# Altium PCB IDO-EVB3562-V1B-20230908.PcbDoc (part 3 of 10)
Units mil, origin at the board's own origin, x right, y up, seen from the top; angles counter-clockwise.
Board outline 5314.96 x 3543.31 mil, 4 copper layers (TOP, L2-VCC, L3-GND, BOTTOM), stack 28.8 mil thick; 747 components, 560 nets, 2514 pads, 1964 vias.
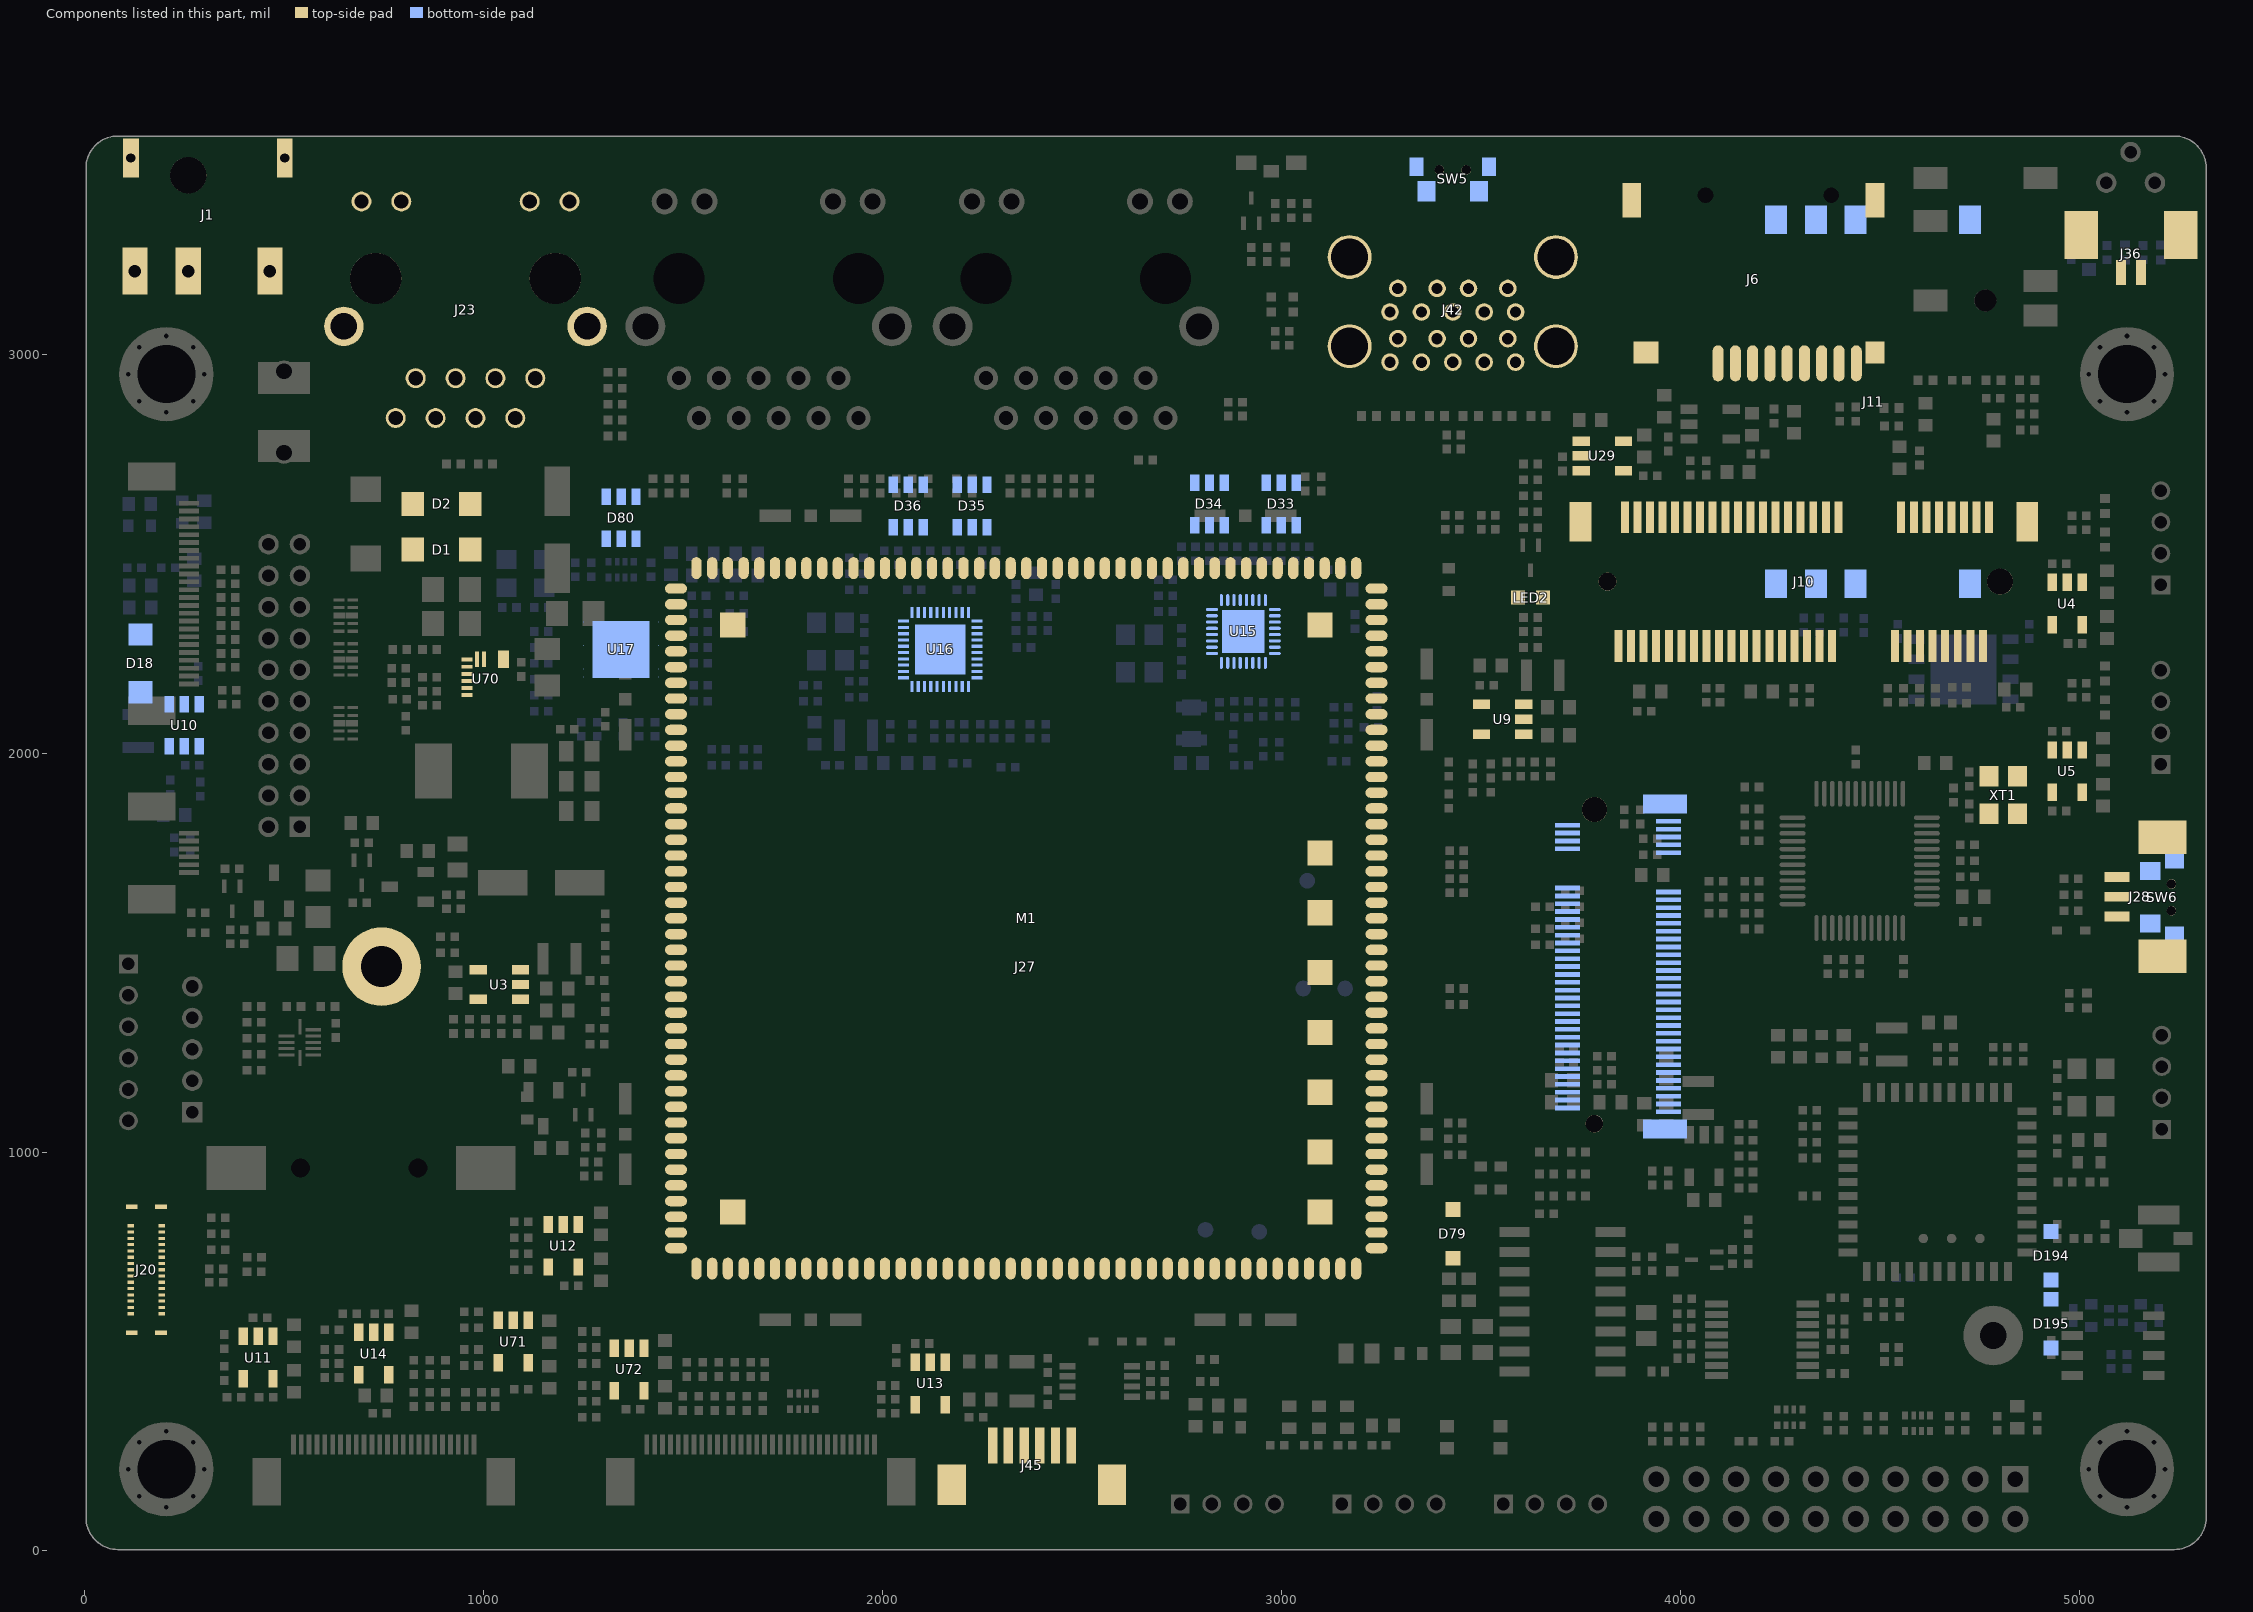
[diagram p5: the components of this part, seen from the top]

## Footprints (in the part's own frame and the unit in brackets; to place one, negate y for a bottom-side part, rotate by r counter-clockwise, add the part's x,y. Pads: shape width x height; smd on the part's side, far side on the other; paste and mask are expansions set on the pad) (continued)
SILKSCREEN_BOTTOM#9 [mm] "SILKSCREEN_BOTTOM"
  oct 0.025x0.025 smd: 1(-2.4,1.751) 2(-2.4,1.251) 3(-2.4,0.751) 4(-2.4,0.25) 5(-2.4,-0.25) 6(-2.4,-0.751) 7(-2.4,-1.251) 8(-2.4,-1.751) 9(-1.751,-2.4) 10(-1.251,-2.4) 11(-0.751,-2.4) 12(-0.25,-2.4) 13(0.25,-2.4) 14(0.751,-2.4) 15(1.251,-2.4) 16(1.751,-2.4) 17(2.4,-1.751) 18(2.4,-1.251) 19(2.4,-0.751) 20(2.4,-0.25) 21(2.4,0.25) 22(2.4,0.751) 23(2.4,1.251) 24(2.4,1.751) 25(1.751,2.4) 26(1.251,2.4) 27(0.751,2.4) 28(0.25,2.4) 29(-0.25,2.4) 30(-0.751,2.4) 31(-1.251,2.4) 32(-1.751,2.4)
  rect 3.607x3.607 smd: 33(0,0)
  TOP region: -1.612,-2.197 -1.612,-2.756 -1.891,-2.756 -1.891,-2.197 -1.891,-2.184 -1.891,-2.184 -1.89,-2.172 -1.889,-2.16 -1.886,-2.148 -1.883,-2.137 -1.878,-2.125 -1.872,-2.115 -1.866,-2.104 -1.858,-2.095 -1.85,-2.086 -1.841,-2.077 -1.831,-2.07 -1.821,-2.063 -1.81,-2.058 -1.799,-2.053 -1.787,-2.049 -1.776,-2.047 -1.763,-2.045 -1.751,-2.045 -1.739,-2.045 -1.727,-2.047 -1.715,-2.049 -1.704,-2.053 -1.692,-2.058 -1.681,-2.063 -1.671,-2.07 -1.662,-2.077 -1.653,-2.086 -1.644,-2.095 -1.637,-2.104 -1.63,-2.115 -1.625,-2.125 -1.62,-2.137 -1.616,-2.148 -1.614,-2.16 -1.612,-2.172 -1.612,-2.184 -1.612,-2.197
  TOP region: -1.612,-2.197 -1.612,-2.756 -1.891,-2.756 -1.891,-2.197 -1.891,-2.184 -1.891,-2.184 -1.89,-2.172 -1.889,-2.16 -1.886,-2.148 -1.883,-2.137 -1.878,-2.125 -1.872,-2.115 -1.866,-2.104 -1.858,-2.095 -1.85,-2.086 -1.841,-2.077 -1.831,-2.07 -1.821,-2.063 -1.81,-2.058 -1.799,-2.053 -1.787,-2.049 -1.776,-2.047 -1.763,-2.045 -1.751,-2.045 -1.739,-2.045 -1.727,-2.047 -1.715,-2.049 -1.704,-2.053 -1.692,-2.058 -1.681,-2.063 -1.671,-2.07 -1.662,-2.077 -1.653,-2.086 -1.644,-2.095 -1.637,-2.104 -1.63,-2.115 -1.625,-2.125 -1.62,-2.137 -1.616,-2.148 -1.614,-2.16 -1.612,-2.172 -1.612,-2.184 -1.612,-2.197
  TOP region: -1.111,-2.197 -1.111,-2.756 -1.391,-2.756 -1.391,-2.197 -1.391,-2.184 -1.391,-2.184 -1.39,-2.172 -1.389,-2.16 -1.386,-2.148 -1.382,-2.137 -1.378,-2.125 -1.372,-2.115 -1.365,-2.104 -1.358,-2.095 -1.35,-2.086 -1.341,-2.077 -1.331,-2.07 -1.321,-2.063 -1.31,-2.058 -1.299,-2.053 -1.287,-2.049 -1.275,-2.047 -1.263,-2.045 -1.251,-2.045 -1.239,-2.045 -1.227,-2.047 -1.215,-2.049 -1.203,-2.053 -1.192,-2.058 -1.181,-2.063 -1.171,-2.07 -1.161,-2.077 -1.152,-2.086 -1.144,-2.095 -1.137,-2.104 -1.13,-2.115 -1.124,-2.125 -1.12,-2.137 -1.116,-2.148 -1.113,-2.16 -1.112,-2.172 -1.111,-2.184 -1.111,-2.197
  TOP region: -1.111,-2.197 -1.111,-2.756 -1.391,-2.756 -1.391,-2.197 -1.391,-2.184 -1.391,-2.184 -1.39,-2.172 -1.389,-2.16 -1.386,-2.148 -1.382,-2.137 -1.378,-2.125 -1.372,-2.115 -1.365,-2.104 -1.358,-2.095 -1.35,-2.086 -1.341,-2.077 -1.331,-2.07 -1.321,-2.063 -1.31,-2.058 -1.299,-2.053 -1.287,-2.049 -1.275,-2.047 -1.263,-2.045 -1.251,-2.045 -1.239,-2.045 -1.227,-2.047 -1.215,-2.049 -1.203,-2.053 -1.192,-2.058 -1.181,-2.063 -1.171,-2.07 -1.161,-2.077 -1.152,-2.086 -1.144,-2.095 -1.137,-2.104 -1.13,-2.115 -1.124,-2.125 -1.12,-2.137 -1.116,-2.148 -1.113,-2.16 -1.112,-2.172 -1.111,-2.184 -1.111,-2.197
  TOP region: -0.611,-2.197 -0.611,-2.756 -0.89,-2.756 -0.89,-2.197 -0.89,-2.184 -0.89,-2.184 -0.89,-2.172 -0.888,-2.16 -0.886,-2.148 -0.882,-2.137 -0.877,-2.125 -0.872,-2.115 -0.865,-2.104 -0.858,-2.095 -0.849,-2.086 -0.84,-2.077 -0.831,-2.07 -0.82,-2.063 -0.81,-2.058 -0.798,-2.053 -0.787,-2.049 -0.775,-2.047 -0.763,-2.045 -0.751,-2.045 -0.738,-2.045 -0.726,-2.047 -0.714,-2.049 -0.703,-2.053 -0.692,-2.058 -0.681,-2.063 -0.67,-2.07 -0.661,-2.077 -0.652,-2.086 -0.644,-2.095 -0.636,-2.104 -0.63,-2.115 -0.624,-2.125 -0.619,-2.137 -0.616,-2.148 -0.613,-2.16 -0.611,-2.172 -0.611,-2.184 -0.611,-2.197
  TOP region: -0.611,-2.197 -0.611,-2.756 -0.89,-2.756 -0.89,-2.197 -0.89,-2.184 -0.89,-2.184 -0.89,-2.172 -0.888,-2.16 -0.886,-2.148 -0.882,-2.137 -0.877,-2.125 -0.872,-2.115 -0.865,-2.104 -0.858,-2.095 -0.849,-2.086 -0.84,-2.077 -0.831,-2.07 -0.82,-2.063 -0.81,-2.058 -0.798,-2.053 -0.787,-2.049 -0.775,-2.047 -0.763,-2.045 -0.751,-2.045 -0.738,-2.045 -0.726,-2.047 -0.714,-2.049 -0.703,-2.053 -0.692,-2.058 -0.681,-2.063 -0.67,-2.07 -0.661,-2.077 -0.652,-2.086 -0.644,-2.095 -0.636,-2.104 -0.63,-2.115 -0.624,-2.125 -0.619,-2.137 -0.616,-2.148 -0.613,-2.16 -0.611,-2.172 -0.611,-2.184 -0.611,-2.197
  TOP region: -0.11,-2.197 -0.11,-2.756 -0.39,-2.756 -0.39,-2.197 -0.39,-2.184 -0.39,-2.184 -0.389,-2.172 -0.388,-2.16 -0.385,-2.148 -0.381,-2.137 -0.377,-2.125 -0.371,-2.115 -0.365,-2.104 -0.357,-2.095 -0.349,-2.086 -0.34,-2.077 -0.33,-2.07 -0.32,-2.063 -0.309,-2.058 -0.298,-2.053 -0.286,-2.049 -0.274,-2.047 -0.262,-2.045 -0.25,-2.045 -0.238,-2.045 -0.226,-2.047 -0.214,-2.049 -0.202,-2.053 -0.191,-2.058 -0.18,-2.063 -0.17,-2.07 -0.16,-2.077 -0.151,-2.086 -0.143,-2.095 -0.136,-2.104 -0.129,-2.115 -0.124,-2.125 -0.119,-2.137 -0.115,-2.148 -0.113,-2.16 -0.111,-2.172 -0.11,-2.184 -0.11,-2.197
  TOP region: -0.11,-2.197 -0.11,-2.756 -0.39,-2.756 -0.39,-2.197 -0.39,-2.184 -0.39,-2.184 -0.389,-2.172 -0.388,-2.16 -0.385,-2.148 -0.381,-2.137 -0.377,-2.125 -0.371,-2.115 -0.365,-2.104 -0.357,-2.095 -0.349,-2.086 -0.34,-2.077 -0.33,-2.07 -0.32,-2.063 -0.309,-2.058 -0.298,-2.053 -0.286,-2.049 -0.274,-2.047 -0.262,-2.045 -0.25,-2.045 -0.238,-2.045 -0.226,-2.047 -0.214,-2.049 -0.202,-2.053 -0.191,-2.058 -0.18,-2.063 -0.17,-2.07 -0.16,-2.077 -0.151,-2.086 -0.143,-2.095 -0.136,-2.104 -0.129,-2.115 -0.124,-2.125 -0.119,-2.137 -0.115,-2.148 -0.113,-2.16 -0.111,-2.172 -0.11,-2.184 -0.11,-2.197
  TOP region: 0.39,-2.197 0.39,-2.756 0.11,-2.756 0.11,-2.197 0.11,-2.184 0.11,-2.184 0.111,-2.172 0.113,-2.16 0.115,-2.148 0.119,-2.137 0.124,-2.125 0.129,-2.115 0.136,-2.104 0.143,-2.095 0.151,-2.086 0.16,-2.077 0.17,-2.07 0.18,-2.063 0.191,-2.058 0.202,-2.053 0.214,-2.049 0.226,-2.047 0.238,-2.045 0.25,-2.045 0.262,-2.045 0.274,-2.047 0.286,-2.049 0.298,-2.053 0.309,-2.058 0.32,-2.063 0.33,-2.07 0.34,-2.077 0.349,-2.086 0.357,-2.095 0.365,-2.104 0.371,-2.115 0.377,-2.125 0.381,-2.137 0.385,-2.148 0.388,-2.16 0.389,-2.172 0.39,-2.184 0.39,-2.197
  TOP region: 0.39,-2.197 0.39,-2.756 0.11,-2.756 0.11,-2.197 0.11,-2.184 0.11,-2.184 0.111,-2.172 0.113,-2.16 0.115,-2.148 0.119,-2.137 0.124,-2.125 0.129,-2.115 0.136,-2.104 0.143,-2.095 0.151,-2.086 0.16,-2.077 0.17,-2.07 0.18,-2.063 0.191,-2.058 0.202,-2.053 0.214,-2.049 0.226,-2.047 0.238,-2.045 0.25,-2.045 0.262,-2.045 0.274,-2.047 0.286,-2.049 0.298,-2.053 0.309,-2.058 0.32,-2.063 0.33,-2.07 0.34,-2.077 0.349,-2.086 0.357,-2.095 0.365,-2.104 0.371,-2.115 0.377,-2.125 0.381,-2.137 0.385,-2.148 0.388,-2.16 0.389,-2.172 0.39,-2.184 0.39,-2.197
  TOP region: 0.89,-2.197 0.89,-2.756 0.611,-2.756 0.611,-2.197 0.611,-2.184 0.611,-2.184 0.611,-2.172 0.613,-2.16 0.616,-2.148 0.619,-2.137 0.624,-2.125 0.63,-2.115 0.636,-2.104 0.644,-2.095 0.652,-2.086 0.661,-2.077 0.67,-2.07 0.681,-2.063 0.692,-2.058 0.703,-2.053 0.714,-2.049 0.726,-2.047 0.738,-2.045 0.751,-2.045 0.763,-2.045 0.775,-2.047 0.787,-2.049 0.798,-2.053 0.81,-2.058 0.82,-2.063 0.831,-2.07 0.84,-2.077 0.849,-2.086 0.858,-2.095 0.865,-2.104 0.872,-2.115 0.877,-2.125 0.882,-2.137 0.886,-2.148 0.888,-2.16 0.89,-2.172 0.89,-2.184 0.89,-2.197
  TOP region: 0.89,-2.197 0.89,-2.756 0.611,-2.756 0.611,-2.197 0.611,-2.184 0.611,-2.184 0.611,-2.172 0.613,-2.16 0.616,-2.148 0.619,-2.137 0.624,-2.125 0.63,-2.115 0.636,-2.104 0.644,-2.095 0.652,-2.086 0.661,-2.077 0.67,-2.07 0.681,-2.063 0.692,-2.058 0.703,-2.053 0.714,-2.049 0.726,-2.047 0.738,-2.045 0.751,-2.045 0.763,-2.045 0.775,-2.047 0.787,-2.049 0.798,-2.053 0.81,-2.058 0.82,-2.063 0.831,-2.07 0.84,-2.077 0.849,-2.086 0.858,-2.095 0.865,-2.104 0.872,-2.115 0.877,-2.125 0.882,-2.137 0.886,-2.148 0.888,-2.16 0.89,-2.172 0.89,-2.184 0.89,-2.197
  TOP region: 1.391,-2.197 1.391,-2.756 1.111,-2.756 1.111,-2.197 1.111,-2.184 1.111,-2.184 1.112,-2.172 1.113,-2.16 1.116,-2.148 1.12,-2.137 1.124,-2.125 1.13,-2.115 1.137,-2.104 1.144,-2.095 1.152,-2.086 1.161,-2.077 1.171,-2.07 1.181,-2.063 1.192,-2.058 1.203,-2.053 1.215,-2.049 1.227,-2.047 1.239,-2.045 1.251,-2.045 1.263,-2.045 1.275,-2.047 1.287,-2.049 1.299,-2.053 1.31,-2.058 1.321,-2.063 1.331,-2.07 1.341,-2.077 1.35,-2.086 1.358,-2.095 1.365,-2.104 1.372,-2.115 1.378,-2.125 1.382,-2.137 1.386,-2.148 1.389,-2.16 1.39,-2.172 1.391,-2.184 1.391,-2.197
  TOP region: 1.391,-2.197 1.391,-2.756 1.111,-2.756 1.111,-2.197 1.111,-2.184 1.111,-2.184 1.112,-2.172 1.113,-2.16 1.116,-2.148 1.12,-2.137 1.124,-2.125 1.13,-2.115 1.137,-2.104 1.144,-2.095 1.152,-2.086 1.161,-2.077 1.171,-2.07 1.181,-2.063 1.192,-2.058 1.203,-2.053 1.215,-2.049 1.227,-2.047 1.239,-2.045 1.251,-2.045 1.263,-2.045 1.275,-2.047 1.287,-2.049 1.299,-2.053 1.31,-2.058 1.321,-2.063 1.331,-2.07 1.341,-2.077 1.35,-2.086 1.358,-2.095 1.365,-2.104 1.372,-2.115 1.378,-2.125 1.382,-2.137 1.386,-2.148 1.389,-2.16 1.39,-2.172 1.391,-2.184 1.391,-2.197
  TOP region: 1.891,-2.197 1.891,-2.756 1.612,-2.756 1.612,-2.197 1.612,-2.184 1.612,-2.184 1.612,-2.172 1.614,-2.16 1.616,-2.148 1.62,-2.137 1.625,-2.125 1.63,-2.115 1.637,-2.104 1.644,-2.095 1.653,-2.086 1.662,-2.077 1.671,-2.07 1.681,-2.063 1.692,-2.058 1.704,-2.053 1.715,-2.049 1.727,-2.047 1.739,-2.045 1.751,-2.045 1.763,-2.045 1.776,-2.047 1.787,-2.049 1.799,-2.053 1.81,-2.058 1.821,-2.063 1.831,-2.07 1.841,-2.077 1.85,-2.086 1.858,-2.095 1.866,-2.104 1.872,-2.115 1.878,-2.125 1.883,-2.137 1.886,-2.148 1.889,-2.16 1.89,-2.172 1.891,-2.184 1.891,-2.197
  TOP region: 1.891,-2.197 1.891,-2.756 1.612,-2.756 1.612,-2.197 1.612,-2.184 1.612,-2.184 1.612,-2.172 1.614,-2.16 1.616,-2.148 1.62,-2.137 1.625,-2.125 1.63,-2.115 1.637,-2.104 1.644,-2.095 1.653,-2.086 1.662,-2.077 1.671,-2.07 1.681,-2.063 1.692,-2.058 1.704,-2.053 1.715,-2.049 1.727,-2.047 1.739,-2.045 1.751,-2.045 1.763,-2.045 1.776,-2.047 1.787,-2.049 1.799,-2.053 1.81,-2.058 1.821,-2.063 1.831,-2.07 1.841,-2.077 1.85,-2.086 1.858,-2.095 1.866,-2.104 1.872,-2.115 1.878,-2.125 1.883,-2.137 1.886,-2.148 1.889,-2.16 1.89,-2.172 1.891,-2.184 1.891,-2.197
  TOP region: -2.197,-1.891 -2.756,-1.891 -2.756,-1.612 -2.197,-1.612 -2.184,-1.612 -2.184,-1.612 -2.172,-1.612 -2.16,-1.614 -2.148,-1.616 -2.137,-1.62 -2.125,-1.625 -2.115,-1.63 -2.104,-1.637 -2.095,-1.644 -2.086,-1.653 -2.077,-1.662 -2.07,-1.671 -2.063,-1.681 -2.058,-1.692 -2.053,-1.704 -2.049,-1.715 -2.047,-1.727 -2.045,-1.739 -2.045,-1.751 -2.045,-1.763 -2.047,-1.776 -2.049,-1.787 -2.053,-1.799 -2.058,-1.81 -2.063,-1.821 -2.07,-1.831 -2.077,-1.841 -2.086,-1.85 -2.095,-1.858 -2.104,-1.866 -2.115,-1.872 -2.125,-1.878 -2.137,-1.883 -2.148,-1.886 -2.16,-1.889 -2.172,-1.89 -2.184,-1.891 -2.197,-1.891
  TOP region: -2.197,-1.891 -2.756,-1.891 -2.756,-1.612 -2.197,-1.612 -2.184,-1.612 -2.184,-1.612 -2.172,-1.612 -2.16,-1.614 -2.148,-1.616 -2.137,-1.62 -2.125,-1.625 -2.115,-1.63 -2.104,-1.637 -2.095,-1.644 -2.086,-1.653 -2.077,-1.662 -2.07,-1.671 -2.063,-1.681 -2.058,-1.692 -2.053,-1.704 -2.049,-1.715 -2.047,-1.727 -2.045,-1.739 -2.045,-1.751 -2.045,-1.763 -2.047,-1.776 -2.049,-1.787 -2.053,-1.799 -2.058,-1.81 -2.063,-1.821 -2.07,-1.831 -2.077,-1.841 -2.086,-1.85 -2.095,-1.858 -2.104,-1.866 -2.115,-1.872 -2.125,-1.878 -2.137,-1.883 -2.148,-1.886 -2.16,-1.889 -2.172,-1.89 -2.184,-1.891 -2.197,-1.891
  TOP region: 2.197,-1.612 2.756,-1.612 2.756,-1.891 2.197,-1.891 2.184,-1.891 2.184,-1.891 2.172,-1.89 2.16,-1.889 2.148,-1.886 2.137,-1.883 2.125,-1.878 2.115,-1.872 2.104,-1.866 2.095,-1.858 2.086,-1.85 2.077,-1.841 2.07,-1.831 2.063,-1.821 2.058,-1.81 2.053,-1.799 2.049,-1.787 2.047,-1.776 2.045,-1.763 2.045,-1.751 2.045,-1.739 2.047,-1.727 2.049,-1.715 2.053,-1.704 2.058,-1.692 2.063,-1.681 2.07,-1.671 2.077,-1.662 2.086,-1.653 2.095,-1.644 2.104,-1.637 2.115,-1.63 2.125,-1.625 2.137,-1.62 2.148,-1.616 2.16,-1.614 2.172,-1.612 2.184,-1.612 2.197,-1.612
  TOP region: 2.197,-1.612 2.756,-1.612 2.756,-1.891 2.197,-1.891 2.184,-1.891 2.184,-1.891 2.172,-1.89 2.16,-1.889 2.148,-1.886 2.137,-1.883 2.125,-1.878 2.115,-1.872 2.104,-1.866 2.095,-1.858 2.086,-1.85 2.077,-1.841 2.07,-1.831 2.063,-1.821 2.058,-1.81 2.053,-1.799 2.049,-1.787 2.047,-1.776 2.045,-1.763 2.045,-1.751 2.045,-1.739 2.047,-1.727 2.049,-1.715 2.053,-1.704 2.058,-1.692 2.063,-1.681 2.07,-1.671 2.077,-1.662 2.086,-1.653 2.095,-1.644 2.104,-1.637 2.115,-1.63 2.125,-1.625 2.137,-1.62 2.148,-1.616 2.16,-1.614 2.172,-1.612 2.184,-1.612 2.197,-1.612
  TOP region: -2.197,-1.391 -2.756,-1.391 -2.756,-1.111 -2.197,-1.111 -2.184,-1.111 -2.184,-1.111 -2.172,-1.112 -2.16,-1.113 -2.148,-1.116 -2.137,-1.12 -2.125,-1.124 -2.115,-1.13 -2.104,-1.137 -2.095,-1.144 -2.086,-1.152 -2.077,-1.161 -2.07,-1.171 -2.063,-1.181 -2.058,-1.192 -2.053,-1.203 -2.049,-1.215 -2.047,-1.227 -2.045,-1.239 -2.045,-1.251 -2.045,-1.263 -2.047,-1.275 -2.049,-1.287 -2.053,-1.299 -2.058,-1.31 -2.063,-1.321 -2.07,-1.331 -2.077,-1.341 -2.086,-1.35 -2.095,-1.358 -2.104,-1.365 -2.115,-1.372 -2.125,-1.378 -2.137,-1.382 -2.148,-1.386 -2.16,-1.389 -2.172,-1.39 -2.184,-1.391 -2.197,-1.391
  TOP region: -2.197,-1.391 -2.756,-1.391 -2.756,-1.111 -2.197,-1.111 -2.184,-1.111 -2.184,-1.111 -2.172,-1.112 -2.16,-1.113 -2.148,-1.116 -2.137,-1.12 -2.125,-1.124 -2.115,-1.13 -2.104,-1.137 -2.095,-1.144 -2.086,-1.152 -2.077,-1.161 -2.07,-1.171 -2.063,-1.181 -2.058,-1.192 -2.053,-1.203 -2.049,-1.215 -2.047,-1.227 -2.045,-1.239 -2.045,-1.251 -2.045,-1.263 -2.047,-1.275 -2.049,-1.287 -2.053,-1.299 -2.058,-1.31 -2.063,-1.321 -2.07,-1.331 -2.077,-1.341 -2.086,-1.35 -2.095,-1.358 -2.104,-1.365 -2.115,-1.372 -2.125,-1.378 -2.137,-1.382 -2.148,-1.386 -2.16,-1.389 -2.172,-1.39 -2.184,-1.391 -2.197,-1.391
  TOP region: 2.197,-1.111 2.756,-1.111 2.756,-1.391 2.197,-1.391 2.184,-1.391 2.184,-1.391 2.172,-1.39 2.16,-1.389 2.148,-1.386 2.137,-1.382 2.125,-1.378 2.115,-1.372 2.104,-1.365 2.095,-1.358 2.086,-1.35 2.077,-1.341 2.07,-1.331 2.063,-1.321 2.058,-1.31 2.053,-1.299 2.049,-1.287 2.047,-1.275 2.045,-1.263 2.045,-1.251 2.045,-1.239 2.047,-1.227 2.049,-1.215 2.053,-1.203 2.058,-1.192 2.063,-1.181 2.07,-1.171 2.077,-1.161 2.086,-1.152 2.095,-1.144 2.104,-1.137 2.115,-1.13 2.125,-1.124 2.137,-1.12 2.148,-1.116 2.16,-1.113 2.172,-1.112 2.184,-1.111 2.197,-1.111
  TOP region: 2.197,-1.111 2.756,-1.111 2.756,-1.391 2.197,-1.391 2.184,-1.391 2.184,-1.391 2.172,-1.39 2.16,-1.389 2.148,-1.386 2.137,-1.382 2.125,-1.378 2.115,-1.372 2.104,-1.365 2.095,-1.358 2.086,-1.35 2.077,-1.341 2.07,-1.331 2.063,-1.321 2.058,-1.31 2.053,-1.299 2.049,-1.287 2.047,-1.275 2.045,-1.263 2.045,-1.251 2.045,-1.239 2.047,-1.227 2.049,-1.215 2.053,-1.203 2.058,-1.192 2.063,-1.181 2.07,-1.171 2.077,-1.161 2.086,-1.152 2.095,-1.144 2.104,-1.137 2.115,-1.13 2.125,-1.124 2.137,-1.12 2.148,-1.116 2.16,-1.113 2.172,-1.112 2.184,-1.111 2.197,-1.111
  TOP region: -2.197,-0.89 -2.756,-0.89 -2.756,-0.611 -2.197,-0.611 -2.184,-0.611 -2.184,-0.611 -2.172,-0.611 -2.16,-0.613 -2.148,-0.616 -2.137,-0.619 -2.125,-0.624 -2.115,-0.63 -2.104,-0.636 -2.095,-0.644 -2.086,-0.652 -2.077,-0.661 -2.07,-0.67 -2.063,-0.681 -2.058,-0.692 -2.053,-0.703 -2.049,-0.714 -2.047,-0.726 -2.045,-0.738 -2.045,-0.751 -2.045,-0.763 -2.047,-0.775 -2.049,-0.787 -2.053,-0.798 -2.058,-0.81 -2.063,-0.82 -2.07,-0.831 -2.077,-0.84 -2.086,-0.849 -2.095,-0.858 -2.104,-0.865 -2.115,-0.872 -2.125,-0.877 -2.137,-0.882 -2.148,-0.886 -2.16,-0.888 -2.172,-0.89 -2.184,-0.89 -2.197,-0.89
  TOP region: -2.197,-0.89 -2.756,-0.89 -2.756,-0.611 -2.197,-0.611 -2.184,-0.611 -2.184,-0.611 -2.172,-0.611 -2.16,-0.613 -2.148,-0.616 -2.137,-0.619 -2.125,-0.624 -2.115,-0.63 -2.104,-0.636 -2.095,-0.644 -2.086,-0.652 -2.077,-0.661 -2.07,-0.67 -2.063,-0.681 -2.058,-0.692 -2.053,-0.703 -2.049,-0.714 -2.047,-0.726 -2.045,-0.738 -2.045,-0.751 -2.045,-0.763 -2.047,-0.775 -2.049,-0.787 -2.053,-0.798 -2.058,-0.81 -2.063,-0.82 -2.07,-0.831 -2.077,-0.84 -2.086,-0.849 -2.095,-0.858 -2.104,-0.865 -2.115,-0.872 -2.125,-0.877 -2.137,-0.882 -2.148,-0.886 -2.16,-0.888 -2.172,-0.89 -2.184,-0.89 -2.197,-0.89
  TOP region: 2.197,-0.611 2.756,-0.611 2.756,-0.89 2.197,-0.89 2.184,-0.89 2.184,-0.89 2.172,-0.89 2.16,-0.888 2.148,-0.886 2.137,-0.882 2.125,-0.877 2.115,-0.872 2.104,-0.865 2.095,-0.858 2.086,-0.849 2.077,-0.84 2.07,-0.831 2.063,-0.82 2.058,-0.81 2.053,-0.798 2.049,-0.787 2.047,-0.775 2.045,-0.763 2.045,-0.751 2.045,-0.738 2.047,-0.726 2.049,-0.714 2.053,-0.703 2.058,-0.692 2.063,-0.681 2.07,-0.67 2.077,-0.661 2.086,-0.652 2.095,-0.644 2.104,-0.636 2.115,-0.63 2.125,-0.624 2.137,-0.619 2.148,-0.616 2.16,-0.613 2.172,-0.611 2.184,-0.611 2.197,-0.611
  TOP region: 2.197,-0.611 2.756,-0.611 2.756,-0.89 2.197,-0.89 2.184,-0.89 2.184,-0.89 2.172,-0.89 2.16,-0.888 2.148,-0.886 2.137,-0.882 2.125,-0.877 2.115,-0.872 2.104,-0.865 2.095,-0.858 2.086,-0.849 2.077,-0.84 2.07,-0.831 2.063,-0.82 2.058,-0.81 2.053,-0.798 2.049,-0.787 2.047,-0.775 2.045,-0.763 2.045,-0.751 2.045,-0.738 2.047,-0.726 2.049,-0.714 2.053,-0.703 2.058,-0.692 2.063,-0.681 2.07,-0.67 2.077,-0.661 2.086,-0.652 2.095,-0.644 2.104,-0.636 2.115,-0.63 2.125,-0.624 2.137,-0.619 2.148,-0.616 2.16,-0.613 2.172,-0.611 2.184,-0.611 2.197,-0.611
  TOP region: -2.197,-0.39 -2.756,-0.39 -2.756,-0.11 -2.197,-0.11 -2.184,-0.11 -2.184,-0.11 -2.172,-0.111 -2.16,-0.113 -2.148,-0.115 -2.137,-0.119 -2.125,-0.124 -2.115,-0.129 -2.104,-0.136 -2.095,-0.143 -2.086,-0.151 -2.077,-0.16 -2.07,-0.17 -2.063,-0.18 -2.058,-0.191 -2.053,-0.202 -2.049,-0.214 -2.047,-0.226 -2.045,-0.238 -2.045,-0.25 -2.045,-0.262 -2.047,-0.274 -2.049,-0.286 -2.053,-0.298 -2.058,-0.309 -2.063,-0.32 -2.07,-0.33 -2.077,-0.34 -2.086,-0.349 -2.095,-0.357 -2.104,-0.365 -2.115,-0.371 -2.125,-0.377 -2.137,-0.381 -2.148,-0.385 -2.16,-0.388 -2.172,-0.389 -2.184,-0.39 -2.197,-0.39
  TOP region: -2.197,-0.39 -2.756,-0.39 -2.756,-0.11 -2.197,-0.11 -2.184,-0.11 -2.184,-0.11 -2.172,-0.111 -2.16,-0.113 -2.148,-0.115 -2.137,-0.119 -2.125,-0.124 -2.115,-0.129 -2.104,-0.136 -2.095,-0.143 -2.086,-0.151 -2.077,-0.16 -2.07,-0.17 -2.063,-0.18 -2.058,-0.191 -2.053,-0.202 -2.049,-0.214 -2.047,-0.226 -2.045,-0.238 -2.045,-0.25 -2.045,-0.262 -2.047,-0.274 -2.049,-0.286 -2.053,-0.298 -2.058,-0.309 -2.063,-0.32 -2.07,-0.33 -2.077,-0.34 -2.086,-0.349 -2.095,-0.357 -2.104,-0.365 -2.115,-0.371 -2.125,-0.377 -2.137,-0.381 -2.148,-0.385 -2.16,-0.388 -2.172,-0.389 -2.184,-0.39 -2.197,-0.39
  TOP region: 2.197,-0.11 2.756,-0.11 2.756,-0.39 2.197,-0.39 2.184,-0.39 2.184,-0.39 2.172,-0.389 2.16,-0.388 2.148,-0.385 2.137,-0.381 2.125,-0.377 2.115,-0.371 2.104,-0.365 2.095,-0.357 2.086,-0.349 2.077,-0.34 2.07,-0.33 2.063,-0.32 2.058,-0.309 2.053,-0.298 2.049,-0.286 2.047,-0.274 2.045,-0.262 2.045,-0.25 2.045,-0.238 2.047,-0.226 2.049,-0.214 2.053,-0.202 2.058,-0.191 2.063,-0.18 2.07,-0.17 2.077,-0.16 2.086,-0.151 2.095,-0.143 2.104,-0.136 2.115,-0.129 2.125,-0.124 2.137,-0.119 2.148,-0.115 2.16,-0.113 2.172,-0.111 2.184,-0.11 2.197,-0.11
  TOP region: 2.197,-0.11 2.756,-0.11 2.756,-0.39 2.197,-0.39 2.184,-0.39 2.184,-0.39 2.172,-0.389 2.16,-0.388 2.148,-0.385 2.137,-0.381 2.125,-0.377 2.115,-0.371 2.104,-0.365 2.095,-0.357 2.086,-0.349 2.077,-0.34 2.07,-0.33 2.063,-0.32 2.058,-0.309 2.053,-0.298 2.049,-0.286 2.047,-0.274 2.045,-0.262 2.045,-0.25 2.045,-0.238 2.047,-0.226 2.049,-0.214 2.053,-0.202 2.058,-0.191 2.063,-0.18 2.07,-0.17 2.077,-0.16 2.086,-0.151 2.095,-0.143 2.104,-0.136 2.115,-0.129 2.125,-0.124 2.137,-0.119 2.148,-0.115 2.16,-0.113 2.172,-0.111 2.184,-0.11 2.197,-0.11
  TOP region: -2.197,0.11 -2.756,0.11 -2.756,0.39 -2.197,0.39 -2.184,0.39 -2.184,0.39 -2.172,0.389 -2.16,0.388 -2.148,0.385 -2.137,0.381 -2.125,0.377 -2.115,0.371 -2.104,0.365 -2.095,0.357 -2.086,0.349 -2.077,0.34 -2.07,0.33 -2.063,0.32 -2.058,0.309 -2.053,0.298 -2.049,0.286 -2.047,0.274 -2.045,0.262 -2.045,0.25 -2.045,0.238 -2.047,0.226 -2.049,0.214 -2.053,0.202 -2.058,0.191 -2.063,0.18 -2.07,0.17 -2.077,0.16 -2.086,0.151 -2.095,0.143 -2.104,0.136 -2.115,0.129 -2.125,0.124 -2.137,0.119 -2.148,0.115 -2.16,0.113 -2.172,0.111 -2.184,0.11 -2.197,0.11
  TOP region: -2.197,0.11 -2.756,0.11 -2.756,0.39 -2.197,0.39 -2.184,0.39 -2.184,0.39 -2.172,0.389 -2.16,0.388 -2.148,0.385 -2.137,0.381 -2.125,0.377 -2.115,0.371 -2.104,0.365 -2.095,0.357 -2.086,0.349 -2.077,0.34 -2.07,0.33 -2.063,0.32 -2.058,0.309 -2.053,0.298 -2.049,0.286 -2.047,0.274 -2.045,0.262 -2.045,0.25 -2.045,0.238 -2.047,0.226 -2.049,0.214 -2.053,0.202 -2.058,0.191 -2.063,0.18 -2.07,0.17 -2.077,0.16 -2.086,0.151 -2.095,0.143 -2.104,0.136 -2.115,0.129 -2.125,0.124 -2.137,0.119 -2.148,0.115 -2.16,0.113 -2.172,0.111 -2.184,0.11 -2.197,0.11
  TOP region: 2.197,0.39 2.756,0.39 2.756,0.11 2.197,0.11 2.184,0.11 2.184,0.11 2.172,0.111 2.16,0.113 2.148,0.115 2.137,0.119 2.125,0.124 2.115,0.129 2.104,0.136 2.095,0.143 2.086,0.151 2.077,0.16 2.07,0.17 2.063,0.18 2.058,0.191 2.053,0.202 2.049,0.214 2.047,0.226 2.045,0.238 2.045,0.25 2.045,0.262 2.047,0.274 2.049,0.286 2.053,0.298 2.058,0.309 2.063,0.32 2.07,0.33 2.077,0.34 2.086,0.349 2.095,0.357 2.104,0.365 2.115,0.371 2.125,0.377 2.137,0.381 2.148,0.385 2.16,0.388 2.172,0.389 2.184,0.39 2.197,0.39
  TOP region: 2.197,0.39 2.756,0.39 2.756,0.11 2.197,0.11 2.184,0.11 2.184,0.11 2.172,0.111 2.16,0.113 2.148,0.115 2.137,0.119 2.125,0.124 2.115,0.129 2.104,0.136 2.095,0.143 2.086,0.151 2.077,0.16 2.07,0.17 2.063,0.18 2.058,0.191 2.053,0.202 2.049,0.214 2.047,0.226 2.045,0.238 2.045,0.25 2.045,0.262 2.047,0.274 2.049,0.286 2.053,0.298 2.058,0.309 2.063,0.32 2.07,0.33 2.077,0.34 2.086,0.349 2.095,0.357 2.104,0.365 2.115,0.371 2.125,0.377 2.137,0.381 2.148,0.385 2.16,0.388 2.172,0.389 2.184,0.39 2.197,0.39
  TOP region: -2.197,0.611 -2.756,0.611 -2.756,0.89 -2.197,0.89 -2.184,0.89 -2.184,0.89 -2.172,0.89 -2.16,0.888 -2.148,0.886 -2.137,0.882 -2.125,0.877 -2.115,0.872 -2.104,0.865 -2.095,0.858 -2.086,0.849 -2.077,0.84 -2.07,0.831 -2.063,0.82 -2.058,0.81 -2.053,0.798 -2.049,0.787 -2.047,0.775 -2.045,0.763 -2.045,0.751 -2.045,0.738 -2.047,0.726 -2.049,0.714 -2.053,0.703 -2.058,0.692 -2.063,0.681 -2.07,0.67 -2.077,0.661 -2.086,0.652 -2.095,0.644 -2.104,0.636 -2.115,0.63 -2.125,0.624 -2.137,0.619 -2.148,0.616 -2.16,0.613 -2.172,0.611 -2.184,0.611 -2.197,0.611
  TOP region: -2.197,0.611 -2.756,0.611 -2.756,0.89 -2.197,0.89 -2.184,0.89 -2.184,0.89 -2.172,0.89 -2.16,0.888 -2.148,0.886 -2.137,0.882 -2.125,0.877 -2.115,0.872 -2.104,0.865 -2.095,0.858 -2.086,0.849 -2.077,0.84 -2.07,0.831 -2.063,0.82 -2.058,0.81 -2.053,0.798 -2.049,0.787 -2.047,0.775 -2.045,0.763 -2.045,0.751 -2.045,0.738 -2.047,0.726 -2.049,0.714 -2.053,0.703 -2.058,0.692 -2.063,0.681 -2.07,0.67 -2.077,0.661 -2.086,0.652 -2.095,0.644 -2.104,0.636 -2.115,0.63 -2.125,0.624 -2.137,0.619 -2.148,0.616 -2.16,0.613 -2.172,0.611 -2.184,0.611 -2.197,0.611
  TOP region: 2.197,0.89 2.756,0.89 2.756,0.611 2.197,0.611 2.184,0.611 2.184,0.611 2.172,0.611 2.16,0.613 2.148,0.616 2.137,0.619 2.125,0.624 2.115,0.63 2.104,0.636 2.095,0.644 2.086,0.652 2.077,0.661 2.07,0.67 2.063,0.681 2.058,0.692 2.053,0.703 2.049,0.714 2.047,0.726 2.045,0.738 2.045,0.751 2.045,0.763 2.047,0.775 2.049,0.787 2.053,0.798 2.058,0.81 2.063,0.82 2.07,0.831 2.077,0.84 2.086,0.849 2.095,0.858 2.104,0.865 2.115,0.872 2.125,0.877 2.137,0.882 2.148,0.886 2.16,0.888 2.172,0.89 2.184,0.89 2.197,0.89
  TOP region: 2.197,0.89 2.756,0.89 2.756,0.611 2.197,0.611 2.184,0.611 2.184,0.611 2.172,0.611 2.16,0.613 2.148,0.616 2.137,0.619 2.125,0.624 2.115,0.63 2.104,0.636 2.095,0.644 2.086,0.652 2.077,0.661 2.07,0.67 2.063,0.681 2.058,0.692 2.053,0.703 2.049,0.714 2.047,0.726 2.045,0.738 2.045,0.751 2.045,0.763 2.047,0.775 2.049,0.787 2.053,0.798 2.058,0.81 2.063,0.82 2.07,0.831 2.077,0.84 2.086,0.849 2.095,0.858 2.104,0.865 2.115,0.872 2.125,0.877 2.137,0.882 2.148,0.886 2.16,0.888 2.172,0.89 2.184,0.89 2.197,0.89
  TOP region: -2.197,1.111 -2.756,1.111 -2.756,1.391 -2.197,1.391 -2.184,1.391 -2.184,1.391 -2.172,1.39 -2.16,1.389 -2.148,1.386 -2.137,1.382 -2.125,1.378 -2.115,1.372 -2.104,1.365 -2.095,1.358 -2.086,1.35 -2.077,1.341 -2.07,1.331 -2.063,1.321 -2.058,1.31 -2.053,1.299 -2.049,1.287 -2.047,1.275 -2.045,1.263 -2.045,1.251 -2.045,1.239 -2.047,1.227 -2.049,1.215 -2.053,1.203 -2.058,1.192 -2.063,1.181 -2.07,1.171 -2.077,1.161 -2.086,1.152 -2.095,1.144 -2.104,1.137 -2.115,1.13 -2.125,1.124 -2.137,1.12 -2.148,1.116 -2.16,1.113 -2.172,1.112 -2.184,1.111 -2.197,1.111
  TOP region: -2.197,1.111 -2.756,1.111 -2.756,1.391 -2.197,1.391 -2.184,1.391 -2.184,1.391 -2.172,1.39 -2.16,1.389 -2.148,1.386 -2.137,1.382 -2.125,1.378 -2.115,1.372 -2.104,1.365 -2.095,1.358 -2.086,1.35 -2.077,1.341 -2.07,1.331 -2.063,1.321 -2.058,1.31 -2.053,1.299 -2.049,1.287 -2.047,1.275 -2.045,1.263 -2.045,1.251 -2.045,1.239 -2.047,1.227 -2.049,1.215 -2.053,1.203 -2.058,1.192 -2.063,1.181 -2.07,1.171 -2.077,1.161 -2.086,1.152 -2.095,1.144 -2.104,1.137 -2.115,1.13 -2.125,1.124 -2.137,1.12 -2.148,1.116 -2.16,1.113 -2.172,1.112 -2.184,1.111 -2.197,1.111
  TOP region: 2.197,1.391 2.756,1.391 2.756,1.111 2.197,1.111 2.184,1.111 2.184,1.111 2.172,1.112 2.16,1.113 2.148,1.116 2.137,1.12 2.125,1.124 2.115,1.13 2.104,1.137 2.095,1.144 2.086,1.152 2.077,1.161 2.07,1.171 2.063,1.181 2.058,1.192 2.053,1.203 2.049,1.215 2.047,1.227 2.045,1.239 2.045,1.251 2.045,1.263 2.047,1.275 2.049,1.287 2.053,1.299 2.058,1.31 2.063,1.321 2.07,1.331 2.077,1.341 2.086,1.35 2.095,1.358 2.104,1.365 2.115,1.372 2.125,1.378 2.137,1.382 2.148,1.386 2.16,1.389 2.172,1.39 2.184,1.391 2.197,1.391
  TOP region: 2.197,1.391 2.756,1.391 2.756,1.111 2.197,1.111 2.184,1.111 2.184,1.111 2.172,1.112 2.16,1.113 2.148,1.116 2.137,1.12 2.125,1.124 2.115,1.13 2.104,1.137 2.095,1.144 2.086,1.152 2.077,1.161 2.07,1.171 2.063,1.181 2.058,1.192 2.053,1.203 2.049,1.215 2.047,1.227 2.045,1.239 2.045,1.251 2.045,1.263 2.047,1.275 2.049,1.287 2.053,1.299 2.058,1.31 2.063,1.321 2.07,1.331 2.077,1.341 2.086,1.35 2.095,1.358 2.104,1.365 2.115,1.372 2.125,1.378 2.137,1.382 2.148,1.386 2.16,1.389 2.172,1.39 2.184,1.391 2.197,1.391
  TOP region: -2.197,1.612 -2.756,1.612 -2.756,1.891 -2.197,1.891 -2.184,1.891 -2.184,1.891 -2.172,1.89 -2.16,1.889 -2.148,1.886 -2.137,1.883 -2.125,1.878 -2.115,1.872 -2.104,1.866 -2.095,1.858 -2.086,1.85 -2.077,1.841 -2.07,1.831 -2.063,1.821 -2.058,1.81 -2.053,1.799 -2.049,1.787 -2.047,1.776 -2.045,1.763 -2.045,1.751 -2.045,1.739 -2.047,1.727 -2.049,1.715 -2.053,1.704 -2.058,1.692 -2.063,1.681 -2.07,1.671 -2.077,1.662 -2.086,1.653 -2.095,1.644 -2.104,1.637 -2.115,1.63 -2.125,1.625 -2.137,1.62 -2.148,1.616 -2.16,1.614 -2.172,1.612 -2.184,1.612 -2.197,1.612
  TOP region: -2.197,1.612 -2.756,1.612 -2.756,1.891 -2.197,1.891 -2.184,1.891 -2.184,1.891 -2.172,1.89 -2.16,1.889 -2.148,1.886 -2.137,1.883 -2.125,1.878 -2.115,1.872 -2.104,1.866 -2.095,1.858 -2.086,1.85 -2.077,1.841 -2.07,1.831 -2.063,1.821 -2.058,1.81 -2.053,1.799 -2.049,1.787 -2.047,1.776 -2.045,1.763 -2.045,1.751 -2.045,1.739 -2.047,1.727 -2.049,1.715 -2.053,1.704 -2.058,1.692 -2.063,1.681 -2.07,1.671 -2.077,1.662 -2.086,1.653 -2.095,1.644 -2.104,1.637 -2.115,1.63 -2.125,1.625 -2.137,1.62 -2.148,1.616 -2.16,1.614 -2.172,1.612 -2.184,1.612 -2.197,1.612
  TOP region: 2.197,1.891 2.756,1.891 2.756,1.612 2.197,1.612 2.184,1.612 2.184,1.612 2.172,1.612 2.16,1.614 2.148,1.616 2.137,1.62 2.125,1.625 2.115,1.63 2.104,1.637 2.095,1.644 2.086,1.653 2.077,1.662 2.07,1.671 2.063,1.681 2.058,1.692 2.053,1.704 2.049,1.715 2.047,1.727 2.045,1.739 2.045,1.751 2.045,1.763 2.047,1.776 2.049,1.787 2.053,1.799 2.058,1.81 2.063,1.821 2.07,1.831 2.077,1.841 2.086,1.85 2.095,1.858 2.104,1.866 2.115,1.872 2.125,1.878 2.137,1.883 2.148,1.886 2.16,1.889 2.172,1.89 2.184,1.891 2.197,1.891
  TOP region: 2.197,1.891 2.756,1.891 2.756,1.612 2.197,1.612 2.184,1.612 2.184,1.612 2.172,1.612 2.16,1.614 2.148,1.616 2.137,1.62 2.125,1.625 2.115,1.63 2.104,1.637 2.095,1.644 2.086,1.653 2.077,1.662 2.07,1.671 2.063,1.681 2.058,1.692 2.053,1.704 2.049,1.715 2.047,1.727 2.045,1.739 2.045,1.751 2.045,1.763 2.047,1.776 2.049,1.787 2.053,1.799 2.058,1.81 2.063,1.821 2.07,1.831 2.077,1.841 2.086,1.85 2.095,1.858 2.104,1.866 2.115,1.872 2.125,1.878 2.137,1.883 2.148,1.886 2.16,1.889 2.172,1.89 2.184,1.891 2.197,1.891
  TOP region: -1.891,2.197 -1.891,2.756 -1.612,2.756 -1.612,2.197 -1.612,2.184 -1.612,2.184 -1.612,2.172 -1.614,2.16 -1.616,2.148 -1.62,2.137 -1.625,2.125 -1.63,2.115 -1.637,2.104 -1.644,2.095 -1.653,2.086 -1.662,2.077 -1.671,2.07 -1.681,2.063 -1.692,2.058 -1.704,2.053 -1.715,2.049 -1.727,2.047 -1.739,2.045 -1.751,2.045 -1.763,2.045 -1.776,2.047 -1.787,2.049 -1.799,2.053 -1.81,2.058 -1.821,2.063 -1.831,2.07 -1.841,2.077 -1.85,2.086 -1.858,2.095 -1.866,2.104 -1.872,2.115 -1.878,2.125 -1.883,2.137 -1.886,2.148 -1.889,2.16 -1.89,2.172 -1.891,2.184 -1.891,2.197
  TOP region: -1.891,2.197 -1.891,2.756 -1.612,2.756 -1.612,2.197 -1.612,2.184 -1.612,2.184 -1.612,2.172 -1.614,2.16 -1.616,2.148 -1.62,2.137 -1.625,2.125 -1.63,2.115 -1.637,2.104 -1.644,2.095 -1.653,2.086 -1.662,2.077 -1.671,2.07 -1.681,2.063 -1.692,2.058 -1.704,2.053 -1.715,2.049 -1.727,2.047 -1.739,2.045 -1.751,2.045 -1.763,2.045 -1.776,2.047 -1.787,2.049 -1.799,2.053 -1.81,2.058 -1.821,2.063 -1.831,2.07 -1.841,2.077 -1.85,2.086 -1.858,2.095 -1.866,2.104 -1.872,2.115 -1.878,2.125 -1.883,2.137 -1.886,2.148 -1.889,2.16 -1.89,2.172 -1.891,2.184 -1.891,2.197
  TOP region: -1.391,2.197 -1.391,2.756 -1.111,2.756 -1.111,2.197 -1.111,2.184 -1.111,2.184 -1.112,2.172 -1.113,2.16 -1.116,2.148 -1.12,2.137 -1.124,2.125 -1.13,2.115 -1.137,2.104 -1.144,2.095 -1.152,2.086 -1.161,2.077 -1.171,2.07 -1.181,2.063 -1.192,2.058 -1.203,2.053 -1.215,2.049 -1.227,2.047 -1.239,2.045 -1.251,2.045 -1.263,2.045 -1.275,2.047 -1.287,2.049 -1.299,2.053 -1.31,2.058 -1.321,2.063 -1.331,2.07 -1.341,2.077 -1.35,2.086 -1.358,2.095 -1.365,2.104 -1.372,2.115 -1.378,2.125 -1.382,2.137 -1.386,2.148 -1.389,2.16 -1.39,2.172 -1.391,2.184 -1.391,2.197
  TOP region: -1.391,2.197 -1.391,2.756 -1.111,2.756 -1.111,2.197 -1.111,2.184 -1.111,2.184 -1.112,2.172 -1.113,2.16 -1.116,2.148 -1.12,2.137 -1.124,2.125 -1.13,2.115 -1.137,2.104 -1.144,2.095 -1.152,2.086 -1.161,2.077 -1.171,2.07 -1.181,2.063 -1.192,2.058 -1.203,2.053 -1.215,2.049 -1.227,2.047 -1.239,2.045 -1.251,2.045 -1.263,2.045 -1.275,2.047 -1.287,2.049 -1.299,2.053 -1.31,2.058 -1.321,2.063 -1.331,2.07 -1.341,2.077 -1.35,2.086 -1.358,2.095 -1.365,2.104 -1.372,2.115 -1.378,2.125 -1.382,2.137 -1.386,2.148 -1.389,2.16 -1.39,2.172 -1.391,2.184 -1.391,2.197
  TOP region: -0.89,2.197 -0.89,2.756 -0.611,2.756 -0.611,2.197 -0.611,2.184 -0.611,2.184 -0.611,2.172 -0.613,2.16 -0.616,2.148 -0.619,2.137 -0.624,2.125 -0.63,2.115 -0.636,2.104 -0.644,2.095 -0.652,2.086 -0.661,2.077 -0.67,2.07 -0.681,2.063 -0.692,2.058 -0.703,2.053 -0.714,2.049 -0.726,2.047 -0.738,2.045 -0.751,2.045 -0.763,2.045 -0.775,2.047 -0.787,2.049 -0.798,2.053 -0.81,2.058 -0.82,2.063 -0.831,2.07 -0.84,2.077 -0.849,2.086 -0.858,2.095 -0.865,2.104 -0.872,2.115 -0.877,2.125 -0.882,2.137 -0.886,2.148 -0.888,2.16 -0.89,2.172 -0.89,2.184 -0.89,2.197
  TOP region: -0.89,2.197 -0.89,2.756 -0.611,2.756 -0.611,2.197 -0.611,2.184 -0.611,2.184 -0.611,2.172 -0.613,2.16 -0.616,2.148 -0.619,2.137 -0.624,2.125 -0.63,2.115 -0.636,2.104 -0.644,2.095 -0.652,2.086 -0.661,2.077 -0.67,2.07 -0.681,2.063 -0.692,2.058 -0.703,2.053 -0.714,2.049 -0.726,2.047 -0.738,2.045 -0.751,2.045 -0.763,2.045 -0.775,2.047 -0.787,2.049 -0.798,2.053 -0.81,2.058 -0.82,2.063 -0.831,2.07 -0.84,2.077 -0.849,2.086 -0.858,2.095 -0.865,2.104 -0.872,2.115 -0.877,2.125 -0.882,2.137 -0.886,2.148 -0.888,2.16 -0.89,2.172 -0.89,2.184 -0.89,2.197
  TOP region: -0.39,2.197 -0.39,2.756 -0.11,2.756 -0.11,2.197 -0.11,2.184 -0.11,2.184 -0.111,2.172 -0.113,2.16 -0.115,2.148 -0.119,2.137 -0.124,2.125 -0.129,2.115 -0.136,2.104 -0.143,2.095 -0.151,2.086 -0.16,2.077 -0.17,2.07 -0.18,2.063 -0.191,2.058 -0.202,2.053 -0.214,2.049 -0.226,2.047 -0.238,2.045 -0.25,2.045 -0.262,2.045 -0.274,2.047 -0.286,2.049 -0.298,2.053 -0.309,2.058 -0.32,2.063 -0.33,2.07 -0.34,2.077 -0.349,2.086 -0.357,2.095 -0.365,2.104 -0.371,2.115 -0.377,2.125 -0.381,2.137 -0.385,2.148 -0.388,2.16 -0.389,2.172 -0.39,2.184 -0.39,2.197
  TOP region: -0.39,2.197 -0.39,2.756 -0.11,2.756 -0.11,2.197 -0.11,2.184 -0.11,2.184 -0.111,2.172 -0.113,2.16 -0.115,2.148 -0.119,2.137 -0.124,2.125 -0.129,2.115 -0.136,2.104 -0.143,2.095 -0.151,2.086 -0.16,2.077 -0.17,2.07 -0.18,2.063 -0.191,2.058 -0.202,2.053 -0.214,2.049 -0.226,2.047 -0.238,2.045 -0.25,2.045 -0.262,2.045 -0.274,2.047 -0.286,2.049 -0.298,2.053 -0.309,2.058 -0.32,2.063 -0.33,2.07 -0.34,2.077 -0.349,2.086 -0.357,2.095 -0.365,2.104 -0.371,2.115 -0.377,2.125 -0.381,2.137 -0.385,2.148 -0.388,2.16 -0.389,2.172 -0.39,2.184 -0.39,2.197
  TOP region: 0.11,2.197 0.11,2.756 0.39,2.756 0.39,2.197 0.39,2.184 0.39,2.184 0.389,2.172 0.388,2.16 0.385,2.148 0.381,2.137 0.377,2.125 0.371,2.115 0.365,2.104 0.357,2.095 0.349,2.086 0.34,2.077 0.33,2.07 0.32,2.063 0.309,2.058 0.298,2.053 0.286,2.049 0.274,2.047 0.262,2.045 0.25,2.045 0.238,2.045 0.226,2.047 0.214,2.049 0.202,2.053 0.191,2.058 0.18,2.063 0.17,2.07 0.16,2.077 0.151,2.086 0.143,2.095 0.136,2.104 0.129,2.115 0.124,2.125 0.119,2.137 0.115,2.148 0.113,2.16 0.111,2.172 0.11,2.184 0.11,2.197
  TOP region: 0.11,2.197 0.11,2.756 0.39,2.756 0.39,2.197 0.39,2.184 0.39,2.184 0.389,2.172 0.388,2.16 0.385,2.148 0.381,2.137 0.377,2.125 0.371,2.115 0.365,2.104 0.357,2.095 0.349,2.086 0.34,2.077 0.33,2.07 0.32,2.063 0.309,2.058 0.298,2.053 0.286,2.049 0.274,2.047 0.262,2.045 0.25,2.045 0.238,2.045 0.226,2.047 0.214,2.049 0.202,2.053 0.191,2.058 0.18,2.063 0.17,2.07 0.16,2.077 0.151,2.086 0.143,2.095 0.136,2.104 0.129,2.115 0.124,2.125 0.119,2.137 0.115,2.148 0.113,2.16 0.111,2.172 0.11,2.184 0.11,2.197
  TOP region: 0.611,2.197 0.611,2.756 0.89,2.756 0.89,2.197 0.89,2.184 0.89,2.184 0.89,2.172 0.888,2.16 0.886,2.148 0.882,2.137 0.877,2.125 0.872,2.115 0.865,2.104 0.858,2.095 0.849,2.086 0.84,2.077 0.831,2.07 0.82,2.063 0.81,2.058 0.798,2.053 0.787,2.049 0.775,2.047 0.763,2.045 0.751,2.045 0.738,2.045 0.726,2.047 0.714,2.049 0.703,2.053 0.692,2.058 0.681,2.063 0.67,2.07 0.661,2.077 0.652,2.086 0.644,2.095 0.636,2.104 0.63,2.115 0.624,2.125 0.619,2.137 0.616,2.148 0.613,2.16 0.611,2.172 0.611,2.184 0.611,2.197
  TOP region: 0.611,2.197 0.611,2.756 0.89,2.756 0.89,2.197 0.89,2.184 0.89,2.184 0.89,2.172 0.888,2.16 0.886,2.148 0.882,2.137 0.877,2.125 0.872,2.115 0.865,2.104 0.858,2.095 0.849,2.086 0.84,2.077 0.831,2.07 0.82,2.063 0.81,2.058 0.798,2.053 0.787,2.049 0.775,2.047 0.763,2.045 0.751,2.045 0.738,2.045 0.726,2.047 0.714,2.049 0.703,2.053 0.692,2.058 0.681,2.063 0.67,2.07 0.661,2.077 0.652,2.086 0.644,2.095 0.636,2.104 0.63,2.115 0.624,2.125 0.619,2.137 0.616,2.148 0.613,2.16 0.611,2.172 0.611,2.184 0.611,2.197
  TOP region: 1.111,2.197 1.111,2.756 1.391,2.756 1.391,2.197 1.391,2.184 1.391,2.184 1.39,2.172 1.389,2.16 1.386,2.148 1.382,2.137 1.378,2.125 1.372,2.115 1.365,2.104 1.358,2.095 1.35,2.086 1.341,2.077 1.331,2.07 1.321,2.063 1.31,2.058 1.299,2.053 1.287,2.049 1.275,2.047 1.263,2.045 1.251,2.045 1.239,2.045 1.227,2.047 1.215,2.049 1.203,2.053 1.192,2.058 1.181,2.063 1.171,2.07 1.161,2.077 1.152,2.086 1.144,2.095 1.137,2.104 1.13,2.115 1.124,2.125 1.12,2.137 1.116,2.148 1.113,2.16 1.112,2.172 1.111,2.184 1.111,2.197
  TOP region: 1.111,2.197 1.111,2.756 1.391,2.756 1.391,2.197 1.391,2.184 1.391,2.184 1.39,2.172 1.389,2.16 1.386,2.148 1.382,2.137 1.378,2.125 1.372,2.115 1.365,2.104 1.358,2.095 1.35,2.086 1.341,2.077 1.331,2.07 1.321,2.063 1.31,2.058 1.299,2.053 1.287,2.049 1.275,2.047 1.263,2.045 1.251,2.045 1.239,2.045 1.227,2.047 1.215,2.049 1.203,2.053 1.192,2.058 1.181,2.063 1.171,2.07 1.161,2.077 1.152,2.086 1.144,2.095 1.137,2.104 1.13,2.115 1.124,2.125 1.12,2.137 1.116,2.148 1.113,2.16 1.112,2.172 1.111,2.184 1.111,2.197
  TOP region: 1.612,2.197 1.612,2.756 1.891,2.756 1.891,2.197 1.891,2.184 1.891,2.184 1.89,2.172 1.889,2.16 1.886,2.148 1.883,2.137 1.878,2.125 1.872,2.115 1.866,2.104 1.858,2.095 1.85,2.086 1.841,2.077 1.831,2.07 1.821,2.063 1.81,2.058 1.799,2.053 1.787,2.049 1.776,2.047 1.763,2.045 1.751,2.045 1.739,2.045 1.727,2.047 1.715,2.049 1.704,2.053 1.692,2.058 1.681,2.063 1.671,2.07 1.662,2.077 1.653,2.086 1.644,2.095 1.637,2.104 1.63,2.115 1.625,2.125 1.62,2.137 1.616,2.148 1.614,2.16 1.612,2.172 1.612,2.184 1.612,2.197
  TOP region: 1.612,2.197 1.612,2.756 1.891,2.756 1.891,2.197 1.891,2.184 1.891,2.184 1.89,2.172 1.889,2.16 1.886,2.148 1.883,2.137 1.878,2.125 1.872,2.115 1.866,2.104 1.858,2.095 1.85,2.086 1.841,2.077 1.831,2.07 1.821,2.063 1.81,2.058 1.799,2.053 1.787,2.049 1.776,2.047 1.763,2.045 1.751,2.045 1.739,2.045 1.727,2.047 1.715,2.049 1.704,2.053 1.692,2.058 1.681,2.063 1.671,2.07 1.662,2.077 1.653,2.086 1.644,2.095 1.637,2.104 1.63,2.115 1.625,2.125 1.62,2.137 1.616,2.148 1.614,2.16 1.612,2.172 1.612,2.184 1.612,2.197
  silkscreen extent -2.68,-2.68 2.68,2.68, body extent -2.76,-2.76 2.76,2.76, height 3.81
SILKSCREEN_TOP#1 [mm] "SILKSCREEN_TOP"
  rect 1.43x1.53 smd: A(-1.84,0) C(1.84,0)
  silkscreen extent -1.75,-1.3 2.42,1.39, body extent -2.66,-1.45 2.66,1.45, height 3.81
SILKSCREEN_TOP#2 [mm] "SILKSCREEN_TOP"
  rect 0.94x0.95 smd: A(-1.55,0) C(1.55,0)
  silkscreen extent -0.6,-0.8 1.97,1.1, body extent -2.02,-0.95 2.02,0.95, height 3.81
SILKSCREEN_TOP#3 [mm] "SILKSCREEN_TOP"
  round 2.3 / inner round 1.524 / far side round 2.3 hole 2.3 unplated: 1(-1.7,-1.301)
  rect 3x1.6 hole 0.8: 2(4.4,3.899) 4(4.4,-4.702)
  rect 3x1.6 / inner round 1.524 / far side rect 3x1.6 hole 0.8: 3(4.4,-1.301)
  rect 2.5x1 hole 0.6: 5(-2.8,4.849) 6(-2.8,-4.951)
  silkscreen extent -8.8,-5.1 5.8,5.1, body extent -5.8,-5.1 5.8,5.1, height 3.81
SILKSCREEN_TOP#4 [mm] "SILKSCREEN_TOP"
  oval 0.7x2.3 smd: 1(2.285,6.625) 2(1.185,6.625) 3(0.085,6.625) 4(-1.015,6.625) 5(-2.115,6.625) 6(-3.215,6.625) 7(-4.315,6.625) 8(-5.415,6.625) 9(-6.515,6.625)
  rect 1.2x1.4 smd: 10(-7.715,5.925)
  rect 1.6x1.4 smd: 11(6.885,5.925)
  rect 1.2x2.2 smd: 12(-7.715,-3.775) 13(7.785,-3.775)
  round 0.1 hole 1: ""(-4.915,-4.075) ""(3.085,-4.075)
  silkscreen extent -7.71,-7.87 7.79,6.62, body extent -8.44,-7.97 8.44,7.97, height 3.81
SILKSCREEN_TOP#5 [mm] "SILKSCREEN_TOP"
  rect 0.508x2.032 smd: 1(11.75,4.05) 2(11.349,-4.149) 3(10.95,4.05) 4(10.549,-4.149) 5(10.15,4.05) 6(9.748,-4.149) 7(9.35,4.05) 8(8.948,-4.149) 9(8.55,4.05) 10(8.148,-4.149) 11(7.749,4.05) 12(7.348,-4.149) 13(6.949,4.05) 14(6.548,-4.149) 15(6.149,4.05) 16(5.751,-4.149) 17(2.149,4.05) 18(1.75,-4.149) 19(1.349,4.05) 20(0.95,-4.149) 21(0.549,4.05) 22(0.15,-4.149) 23(-0.252,4.05) 24(-0.65,-4.149) 25(-1.052,4.05) 26(-1.45,-4.149) 27(-1.852,4.05) 28(-2.25,-4.149) 29(-2.652,4.05) 30(-3.05,-4.149) 31(-3.452,4.05) 32(-3.851,-4.149) 33(-4.252,4.05) 34(-4.651,-4.149) 35(-5.049,4.05) 36(-5.451,-4.149) 37(-5.852,4.05) 38(-6.251,-4.149) 39(-6.65,4.05) 40(-7.051,-4.149) 41(-7.45,4.05) 42(-7.851,-4.149) 43(-8.25,4.05) 44(-8.651,-4.149) 45(-9.05,4.05) 46(-9.451,-4.149) 47(-9.85,4.05) 48(-10.251,-4.149) 49(-10.65,4.05) 50(-11.051,-4.149) 51(-11.45,4.05) 52(-11.852,-4.149)
  round 1.651 / inner round 1.524 / far side round 1.651 hole 1.651 unplated: 53(12.448,-0.049)
  round 1.143 / inner round 1.524 / far side round 1.143 hole 1.143 unplated: 54(-12.55,-0.049)
  rect 1.397x2.54 smd: 55(-14.275,3.761) 56(14.173,3.761)
  Multi-Layer keep-out region: 13.665,-0.049 13.624,0.265 13.502,0.559 13.309,0.81 13.057,1.004 12.764,1.125 12.449,1.167 12.135,1.125 11.841,1.004 11.841,1.004 11.589,0.81 11.396,0.559 11.275,0.265 11.233,-0.049 11.275,-0.364 11.396,-0.658 11.589,-0.909 11.841,-1.103 11.841,-1.103 12.135,-1.224 12.449,-1.266 12.764,-1.224 13.057,-1.103 13.309,-0.909 13.502,-0.658 13.624,-0.364 13.665,-0.049
  Multi-Layer keep-out region: -11.589,-0.049 -11.622,0.199 -11.718,0.431 -11.871,0.63 -12.07,0.783 -12.302,0.879 -12.551,0.912 -12.8,0.879 -13.032,0.783 -13.032,0.783 -13.231,0.63 -13.384,0.431 -13.48,0.199 -13.512,-0.049 -13.48,-0.298 -13.384,-0.53 -13.231,-0.729 -13.032,-0.882 -13.032,-0.882 -12.8,-0.978 -12.551,-1.011 -12.302,-0.978 -12.07,-0.882 -11.871,-0.729 -11.718,-0.53 -11.622,-0.298 -11.589,-0.049
  silkscreen extent -15.05,-51 14.95,3.18, body extent -16.05,-5.35 16.05,5.35, height 3.81
SILKSCREEN_TOP#6 [mm] "SILKSCREEN_TOP"
  rect 0.2x0.42 smd: 1(-2.8,0.675) 2(-2.8,-1.305) 3(-2.4,0.675) 4(-2.4,-1.305) 5(-2,0.675) 6(-2,-1.305) 7(-1.6,0.675) 8(-1.6,-1.305) 9(-1.2,0.675) 10(-1.2,-1.305) 11(-0.8,0.675) 12(-0.8,-1.305) 13(-0.4,0.675) 14(-0.4,-1.305) 15(0,0.675) 16(0,-1.305) 17(0.4,0.675) 18(0.4,-1.305) 19(0.8,0.675) 20(0.8,-1.305) 21(1.2,0.675) 22(1.2,-1.305) 23(1.6,0.675) 24(1.6,-1.305) 25(2,0.675) 26(2,-1.305) 27(2.4,0.675) 28(2.4,-1.305) 29(2.8,0.675) 30(2.8,-1.305)
  rect 0.3x0.75 smd: 31(-4.01,0.61) 32(-4.01,-1.24) 33(4.01,-1.24) 34(4.01,0.61)
  silkscreen extent -4.44,-1.59 4.44,1.59, body extent -4.57,-1.72 4.57,1.72, height 3.81
SILKSCREEN_TOP#7 [mm] "SILKSCREEN_TOP"
  round 1.27 / inner round 1.524 / far side round 1.27 hole 0.914: 1(-4.445,6.45) 2(-3.175,8.99) 3(-1.905,6.45) 4(-0.635,8.99) 5(0.635,6.45) 6(1.905,8.99) 7(3.175,6.45) 9(-6.625,-4.8) 10(-4.085,-4.8) 11(4.085,-4.8) 12(6.625,-4.8)
  round 1.27 hole 0.914: 8(4.445,8.99)
  round 2.5 hole 1.7: 13(-7.745,3.15) 14(7.745,3.15)
  round 3.25 / inner round 1.524 / far side round 3.25 hole 3.25 unplated: 15(-5.715,0.1) 16(5.715,0.1)
  Multi-Layer keep-out region: -7.604,0.1 -7.567,-0.268 -7.46,-0.623 -7.285,-0.949 -7.051,-1.236 -6.764,-1.47 -6.438,-1.645 -6.083,-1.752 -5.715,-1.789 -5.347,-1.752 -4.992,-1.645 -4.775,-1.529 -4.775,-1.529 -4.666,-1.47 -4.379,-1.236 -4.145,-0.949 -3.97,-0.623 -3.863,-0.268 -3.826,0.1 -3.863,0.468 -3.97,0.823 -4.145,1.149 -4.379,1.436 -4.666,1.67 -4.775,1.729 -4.775,1.729 -4.992,1.845 -5.347,1.952 -5.715,1.989 -6.083,1.952 -6.438,1.845 -6.764,1.67 -7.051,1.436 -7.285,1.149 -7.46,0.823 -7.567,0.468 -7.604,0.1
  Multi-Layer keep-out region: 3.826,0.1 3.863,-0.268 3.97,-0.623 4.145,-0.949 4.379,-1.236 4.666,-1.47 4.992,-1.645 5.347,-1.752 5.715,-1.789 6.083,-1.752 6.438,-1.645 6.655,-1.529 6.655,-1.529 6.764,-1.47 7.051,-1.236 7.285,-0.949 7.46,-0.623 7.567,-0.268 7.604,0.1 7.567,0.468 7.46,0.823 7.285,1.149 7.051,1.436 6.764,1.67 6.655,1.729 6.655,1.729 6.438,1.845 6.083,1.952 5.715,1.989 5.347,1.952 4.992,1.845 4.666,1.67 4.379,1.436 4.145,1.149 3.97,0.823 3.863,0.468 3.826,0.1
  silkscreen extent -7.8,-10.8 7.8,10.8, body extent -7.8,-10.8 7.8,10.8, height 3.81
SILKSCREEN_TOP#8 [mm] "SILKSCREEN_TOP"
  rect 0.635x1.6 smd: 1(-1.25,2.3) 2(0,2.3) 3(1.25,2.3)
  rect 2.134x3.048 smd: 4(-3.8,-0.6) 5(3.8,-0.6)
  silkscreen extent -4.3,-3.2 4.3,1.5, body extent -4.3,-3.2 4.3,3.2, height 3.81
SILKSCREEN_TOP#9 [mm] "SILKSCREEN_TOP"
  rect 0.635x1.6 smd: 1(-0.625,1.292) 2(0.625,1.292)
  rect 2.134x3.048 smd: 3(-3.175,-1.1) 4(3.175,-1.1)
  silkscreen extent -3.7,-2.7 3.7,1, body extent -3.7,-2.7 3.7,2.7, height 3.81
SILKSCREEN_TOP#10 [mm] "SILKSCREEN_TOP"
  round 1.118 / inner round 1.524 / far side round 1.118 hole 0.711: 1(-3.5,2.65) 2(-1,2.65) 3(1,2.65) 5(4,4.15) 6(2,4.15) 8(-2,4.15) 9(-4,4.15) 10(-3.5,5.85) 11(-1,5.85) 12(1,5.85) 14(4,7.35) 15(2,7.35) 17(-2,7.35) 18(-4,7.35)
  round 1.118 hole 0.711: 4(3.5,2.65) 7(0,4.15) 13(3.5,5.85) 16(0,7.35)
  round 2.794 hole 2.362: 19(-6.57,6.33) 20(6.57,6.33) 21(6.57,0.65) 22(-6.57,0.65)
  silkscreen extent -7.3,-8.95 7.3,8.95, body extent -7.4,-9.05 7.4,9.05, height 3.81
SILKSCREEN_TOP#11 [mm] "SILKSCREEN_TOP"
  rect 0.6x2.3 smd: 1(2.5,2.65) 2(1.5,2.65) 3(0.5,2.65) 4(-0.5,2.65) 5(-1.5,2.65) 6(-2.5,2.65)
  rect 1.8x2.6 smd: 7(5.1,0.15) 8(-5.1,0.15)
  silkscreen extent -6.3,-3.85 6.3,4.47, body extent -6.3,-3.85 6.3,3.85, height 3.81
SILKSCREEN_TOP#12 [mm] "SILKSCREEN_TOP"
  rect 0.9x0.9 smd: A(-0.8,0) C(0.8,0)
  silkscreen extent -2.16,-0.65 1.4,0.65
SILKSCREEN_TOP#13 [mm] "SILKSCREEN_TOP"
  oval 1.4x0.66 smd: 1(22.3,-21) 2(22.3,-20) 3(22.3,-19) 4(22.3,-18) 5(22.3,-17) 6(22.3,-16) 7(22.3,-15) 8(22.3,-14) 9(22.3,-13) 10(22.3,-12) 11(22.3,-11) 12(22.3,-10) 13(22.3,-9) 14(22.3,-8) 15(22.3,-7) 16(22.3,-6) 17(22.3,-5) 18(22.3,-4) 19(22.3,-3) 20(22.3,-2) 21(22.3,-1) 22(22.3,0) 23(22.3,1) 24(22.3,2) 25(22.3,3) 26(22.3,4) 27(22.3,5) 28(22.3,6) 29(22.3,7) 30(22.3,8) 31(22.3,9) 32(22.3,10) 33(22.3,11) 34(22.3,12) 35(22.3,13) 36(22.3,14) 37(22.3,15) 38(22.3,16) 39(22.3,17) 40(22.3,18) 41(22.3,19) 42(22.3,20) 43(22.3,21) 87(-22.3,21) 88(-22.3,20) 89(-22.3,19) 90(-22.3,18) 91(-22.3,17) 92(-22.3,16) 93(-22.3,15) 94(-22.3,14) 95(-22.3,13) 96(-22.3,12) 97(-22.3,11) 98(-22.3,10) 99(-22.3,9) 100(-22.3,8) 101(-22.3,7) 102(-22.3,6) 103(-22.3,5) 104(-22.3,4) 105(-22.3,3) 106(-22.3,2) 107(-22.3,1) 108(-22.3,0) 109(-22.3,-1) 110(-22.3,-2) 111(-22.3,-3) 112(-22.3,-4) 113(-22.3,-5) 114(-22.3,-6) 115(-22.3,-7) 116(-22.3,-8) 117(-22.3,-9) 118(-22.3,-10) 119(-22.3,-11) 120(-22.3,-12) 121(-22.3,-13) 122(-22.3,-14) 123(-22.3,-15) 124(-22.3,-16) 125(-22.3,-17) 126(-22.3,-18) 127(-22.3,-19) 128(-22.3,-20) 129(-22.3,-21)
  oval 0.66x1.4 smd: 44(21,22.3) 45(20,22.3) 46(19,22.3) 47(18,22.3) 48(17,22.3) 49(16,22.3) 50(15,22.3) 51(14,22.3) 52(13,22.3) 53(12,22.3) 54(11,22.3) 55(10,22.3) 56(9,22.3) 57(8,22.3) 58(7,22.3) 59(6,22.3) 60(5,22.3) 61(4,22.3) 62(3,22.3) 63(2,22.3) 64(1,22.3) 65(0,22.3) 66(-1,22.3) 67(-2,22.3) 68(-3,22.3) 69(-4,22.3) 70(-5,22.3) 71(-6,22.3) 72(-7,22.3) 73(-8,22.3) 74(-9,22.3) 75(-10,22.3) 76(-11,22.3) 77(-12,22.3) 78(-13,22.3) 79(-14,22.3) 80(-15,22.3) 81(-16,22.3) 82(-17,22.3) 83(-18,22.3) 84(-19,22.3) 85(-20,22.3) 86(-21,22.3) 130(-21,-22.3) 131(-20,-22.3) 132(-19,-22.3) 133(-18,-22.3) 134(-17,-22.3) 135(-16,-22.3) 136(-15,-22.3) 137(-14,-22.3) 138(-13,-22.3) 139(-12,-22.3) 140(-11,-22.3) 141(-10,-22.3) 142(-9,-22.3) 143(-8,-22.3) 144(-7,-22.3) 145(-6,-22.3) 146(-5,-22.3) 147(-4,-22.3) 148(-3,-22.3) 149(-2,-22.3) 150(-1,-22.3) 151(0,-22.3) 152(1,-22.3) 153(2,-22.3) 154(3,-22.3) 155(4,-22.3) 156(5,-22.3) 157(6,-22.3) 158(7,-22.3) 159(8,-22.3) 160(9,-22.3) 161(10,-22.3) 162(11,-22.3) 163(12,-22.3) 164(13,-22.3) 165(14,-22.3) 166(15,-22.3) 167(16,-22.3) 168(17,-22.3) 169(18,-22.3) 170(19,-22.3) 171(20,-22.3) 172(21,-22.3)
  rect 1.6x1.6 smd: 173(18.69,-18.69) 174(18.69,-14.88) 175(18.69,-11.07) 176(18.69,-7.26) 177(18.69,-3.45) 178(18.69,0.36) 179(18.69,4.17) 180(18.69,18.69) 181(-18.69,18.69) 182(-18.69,-18.69)
  Multi-Layer keep-out region: 1.5,-13 1.5,-1 -14.5,-1 -14.5,-13 1.5,-13
  Multi-Layer keep-out region: -19.259,-19.82 -19.302,-19.605 -19.423,-19.423 -19.605,-19.302 -19.82,-19.259 -20.035,-19.302 -20.096,-19.343 -20.096,-19.343 -20.217,-19.423 -20.338,-19.605 -20.381,-19.82 -20.338,-20.035 -20.217,-20.217 -20.096,-20.297 -20.096,-20.297 -20.035,-20.338 -19.82,-20.381 -19.605,-20.338 -19.423,-20.217 -19.302,-20.035 -19.259,-19.82
  Multi-Layer keep-out region: 20.381,19.82 20.338,20.035 20.217,20.217 20.035,20.338 19.82,20.381 19.605,20.338 19.544,20.297 19.544,20.297 19.423,20.217 19.302,20.035 19.259,19.82 19.302,19.605 19.423,19.423 19.544,19.343 19.544,19.343 19.605,19.302 19.82,19.259 20.035,19.302 20.217,19.423 20.338,19.605 20.381,19.82
  silkscreen extent -22.5,-22.5 24,22.5, body extent -22.5,-22.5 22.5,22.5, height 3.81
